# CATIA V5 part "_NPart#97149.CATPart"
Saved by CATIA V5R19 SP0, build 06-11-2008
Part number: Perfiles Tarima 3 Sim_Predeterminado<Como mecanizada>
Revision: ANY
Definition: UNKNOWN
Nomenclature: Perfiles Tarima 3 Sim_Predeterminado<Como mecanizada>
Source: Unknown
Bounding box of the stored display mesh (mm): x -500 to 500, y 0 to 2020, z -2200 to 2200
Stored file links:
  C:\Users\Fran Robles\Documents\My Dropbox\DOCS ESI\Aernnova\Industrializacion 3D\Plataforma barcas\_NPart#97149.CATPart
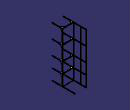
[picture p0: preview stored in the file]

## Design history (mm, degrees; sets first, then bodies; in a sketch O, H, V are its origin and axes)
Body1 "NONE" (main body)
  Solid1: solid without history
Body2 "NONE"
  Solid2: solid without history
Body3 "NONE"
  Solid3: solid without history
Body4 "NONE"
  Solid4: solid without history
Body5 "NONE"
  Solid5: solid without history
Body6 "NONE"
  Solid6: solid without history
Body7 "NONE"
  Solid7: solid without history
Body8 "NONE"
  Solid8: solid without history
Body9 "NONE"
  Solid9: solid without history
Body10 "NONE"
  Solid10: solid without history
Body11 "NONE"
  Solid11: solid without history
Body12 "NONE"
  Solid12: solid without history
Body13 "NONE"
  Solid13: solid without history
Body14 "NONE"
  Solid14: solid without history
Body15 "NONE"
  Solid15: solid without history
Body16 "NONE"
  Solid16: solid without history
Body17 "NONE"
  Solid17: solid without history
Body18 "NONE"
  Solid18: solid without history
Body19 "NONE"
  Solid19: solid without history
Body20 "NONE"
  Solid20: solid without history
Body21 "NONE"
  Solid21: solid without history
Body22 "NONE"
  Solid22: solid without history
Body23 "NONE"
  Solid23: solid without history
Body24 "NONE"
  Solid24: solid without history
Body25 "NONE"
  Solid25: solid without history
Body26 "NONE"
  Solid26: solid without history
Body27 "NONE"
  Solid27: solid without history
Body28 "NONE"
  Solid28: solid without history
Body29 "NONE"
  Solid29: solid without history
Body30 "NONE"
  Solid30: solid without history
Body31 "NONE"
  Solid31: solid without history
Body32 "NONE"
  Solid32: solid without history
Body33 "NONE"
  Solid33: solid without history
Body34 "NONE"
  Solid34: solid without history
Body35 "NONE"
  Solid35: solid without history
Body36 "NONE"
  Solid36: solid without history
Body37 "NONE"
  Solid37: solid without history
Body38 "NONE"
  Solid38: solid without history
Body39 "NONE"
  Solid39: solid without history
Body40 "NONE"
  Solid40: solid without history
Body41 "NONE"
  Solid41: solid without history
Body42 "NONE"
  Solid42: solid without history
Body43 "NONE"
  Solid43: solid without history
Body44 "NONE"
  Solid44: solid without history
Body45 "NONE"
  Solid45: solid without history
Body46 "NONE"
  Solid46: solid without history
